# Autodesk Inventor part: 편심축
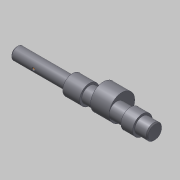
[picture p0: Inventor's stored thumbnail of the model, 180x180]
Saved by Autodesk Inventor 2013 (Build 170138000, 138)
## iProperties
Company: 한국ATC센터
Created: 2015-12
Part Number: 편심축
Document SubType Name: Modeling
Designer: mdu
Density: 7.86 g/cm^3
Mass: 225.444 g
Surface Area: 81.7075 cm^2
Volume: 28.6825 cm^3
Material: 강철, 연강
Author: mdu
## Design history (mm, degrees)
sketch "스케치1"
  geometry: L1 (-86, 0)-(86, 0); L2 (-86, 0)-(-86, 6); L3 (-86, 6)-(-32, 6); L4 (-32, 6)-(-32, 9.5); L5 (-32, 9.5)-(-15.5, 9.5); L6 (-15.5, 9.5)-(-15.5, 7.5); L7 (-15.5, 7.5)-(48, 7.5); L8 (86, 6)-(86, 0); L9 (36, 7.5)-(36, 9.5); L10 (36, 9.5)-(24.5, 9.5); L11 (24.5, 9.5)-(24.5, 7.5); L12 (48, 7.5)-(48, 6); L13 (48, 6)-(86, 6); 2 further points
  constraints: 26 end point, 6 parallel, 6 perpendicular, 2 point on line, 1 coincident, 1 horizontal, 1 midpoint
  dimensions: "d1" = 12 diameter of L3 L1; "d2" = 15 diameter of L7 L1; "d4" = 16.5 distance of L4.end L5.end; "d5" = 19 diameter of L5 L1; "d24" = 11.5 distance of L9.end L10.end; "d25" = 19 diameter of L10 L1; "d27" = 40 distance between parallel lines of L11 L6; "d28" = 54 distance of L2.end L3.end; "d29" = 50 distance between parallel lines of L8 L9; "d41" = 38 distance between parallel lines of L8 L12; "d42" = 12 diameter of L13 L1
revolve "회전1" stored, may be unused: angle "d6" = 90 deg
node "작업 평면1"
sketch "스케치2"
  geometry: C1 r 7.5 at (0, 0) reference; C2 r 12.5 at (0, 5); 1 further point
  constraints: 1 centre point, 1 tangent, 1 vertical alignment
  dimensions: "d9" = 25 diameter of C2
extrude "돌출1" join sketch "스케치2" distance "d10" = 18; taper "d11" = 0 deg
chamfer "모따기1" distance "d12" = 1; stored, may be unused: second distance "d13" = 2, angle "d14" = 45 deg
node "작업 평면2"
sketch "스케치3"
  geometry: L1 (7, -2)-(21, -2); L2 (21, 2)-(7, 2); L3 (27, 5)-(27, -5) reference; A1 r 2 centre (21, 0) between (21, -2) and (21, 2); A2 r 2 centre (7, 0) between (7, 2) and (7, -2); 2 further points
  constraints: 4 end point, 4 point on circle, 4 tangent, 2 centre point, 1 horizontal, 1 horizontal alignment, 1 midpoint, 1 parallel
  dimensions: "d18" = 4 distance edge to line of A1 L3; "d19" = 4 distance between parallel lines of L2 L1; "d20" = 18 dimension on A1 A2
extrude "돌출2" cut sketch "스케치3" distance "d21" = 2.5; taper "d22" = 0 deg
revolve "회전2" stored, may be unused: angle "d26" = 90 deg
node "작업 평면3"
sketch "스케치4"
  geometry: L1 (44, 5)-(44, -5) reference; 2 further points
  constraints: 1 horizontal alignment
  dimensions: "d30" = 12 distance from line of point (32, 0) L1
hole "구멍1" sketch "스케치4" at (32, 0) diameter "d31" = 6; stored, may be unused: countersink angle "d35" = 90 deg, drill point angle "d37" = 118 deg; dims "d32" = 6, "d33" = 14, "d34" = 3, "d36" = 8
node "작업 평면4"
sketch "스케치5"
  geometry: C1 r 3 at (32, 0) reference; C2 r 8 at (32, 0); 2 further points
  constraints: 1 centre point, 1 coincident, 1 other
  dimensions: "d38" = 16 diameter of C2
extrude "돌출3" cut sketch "스케치5" distance "d39" = 3; taper "d40" = 0 deg
sketch "스케치6"
  geometry: L1 (-85, -6)-(-32, -6) reference; L2 (-86, -5)-(-86, 5) reference; L3 (-85, 6)-(-32, 6) reference; L4 (-64, 6)-(-64, -6); L5 (-64, -6)-(-62.5, -6); L6 (-64, -4.5)-(-62.5, -6); L7 (-64, -6)-(-64, -4.5); 2 further points
  constraints: 8 end point, 4 point on line, 2 perpendicular, 1 coincident
  dimensions: "d43" = 22 distance between parallel lines of L4 L2; "d44" = 45 deg angle of L6 L7; "d45" = 3 diameter of L5.end L4
revolve "회전3" stored, may be unused: angle "d46" = 90 deg
node "작업점1"
chamfer "모따기3" distance "d47" = 0.5; stored, may be unused: second distance "d48" = 2, angle "d49" = 45 deg
sketch "스케치7"
  geometry: C1 r 7.5 at (0, 0) reference; 1 further point
extrude "돌출4" cut sketch "스케치7" stored distance "d50" = 10; taper "d51" = 0 deg
chamfer "모따기4" distance "d52" = 1; stored, may be unused: second distance "d53" = 2, angle "d54" = 45 deg
node "작업 평면6"
node "솔리드1"
node "투영된 루프1"
other parameters: "d7" = 8.5
